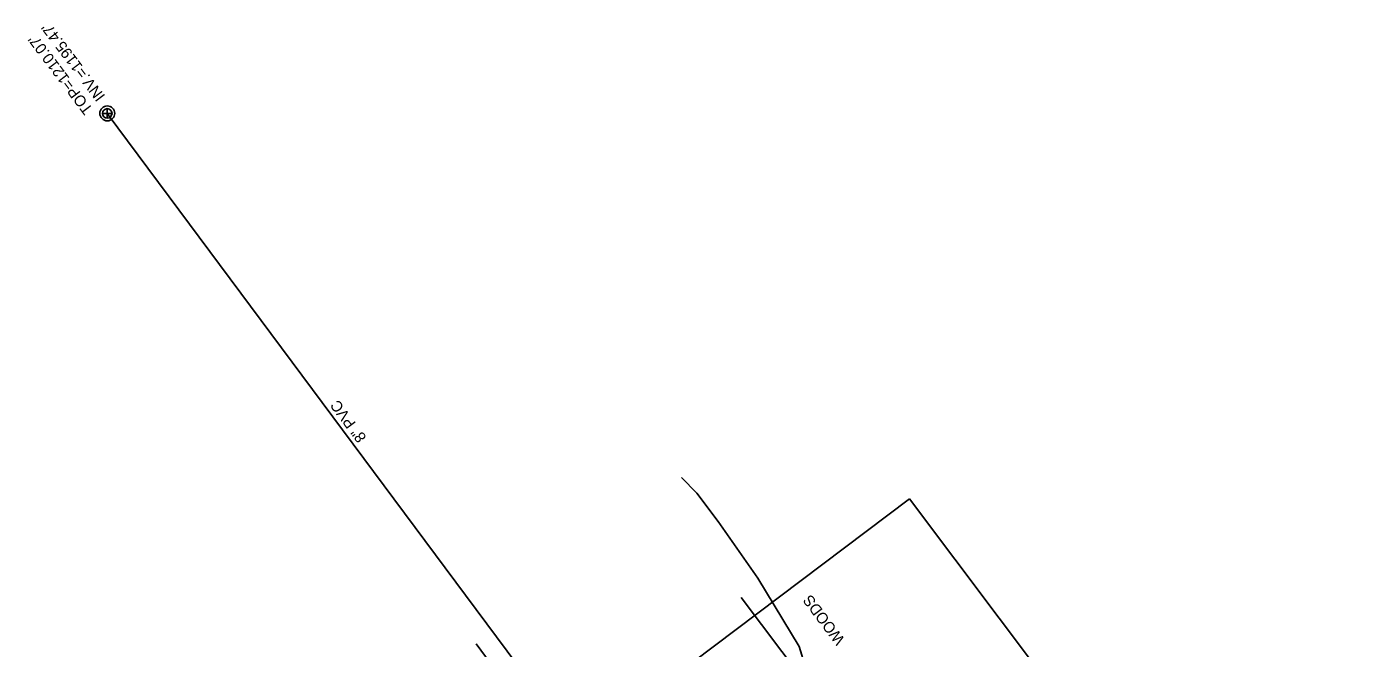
# Model space of a CAD drawing. Extents: x 1262092 to 1264624, y 774970 to 778314.
# Drawn here: x 1262121.8 to 1262603.1, y 778088.7 to 778313.7 of the extents above; entities that cross this region are included whole.
import ezdxf

# ---------------------------------------------------------------- set-up
doc = ezdxf.new("R2010")
doc.units = 0
for name, color, linetype in [('COGO Default Parcel', 7, 'Continuous'), ('Exist Right of Way Line', 7, 'Continuous'), ('Exist Roads EOP', 7, 'Continuous'), ('Exist Utilities Sanitary Sewer Manhole CELL', 7, 'Continuous'), ('Exist Utilities Sanitary Sewer Manhole Text', 7, 'Continuous'), ('Exist Utilities Sanitary Sewer UG Line', 7, 'Continuous'), ('Exist Utilities Sanitary Sewer UG Line Text', 7, 'Continuous'), ('Exist Vegetation Woods Line Text', 7, 'Continuous'), ('Prop Conc 5in Monolithic Keyed In Island', 7, 'Continuous')]:
    doc.layers.add(name, color=color, linetype=linetype)

# ---------------------------------------------------------------- blocks, each defined once
blk = doc.blocks.new('EXIST UTILITIES SANITARY SEWER MANHOLE')
at = {"layer": 'Exist Utilities Sanitary Sewer Manhole CELL'}
blk.add_lwpolyline([(0, 0.03425), (0, -0.03425), (0, 0), (0.03425, 0), (-0.03425, 0)], dxfattribs=at)
for radius in [0.05389, 0.03425]:
    blk.add_circle((0, 0), radius, dxfattribs=at)

msp = doc.modelspace()

# ---------------------------------------------------------------- linework, layer by layer
at = {"layer": 'COGO Default Parcel'}
for p, q in [((1262121.77, 777902.18), (1262441.33, 778142.77)), ((1262441.33, 778142.77), (1263481.78, 776760.76))]:
    msp.add_line(p, q, dxfattribs=at)
at = {"layer": 'Exist Right of Way Line'}
msp.add_line((1262380.46, 778107.12), (1263428.45, 776715.75), dxfattribs=at)
at = {"layer": 'Exist Roads EOP'}
msp.add_lwpolyline([(1262311.57, 778054.09), (1262307.15, 778059.68), (1262299.95, 778069.33), (1262289.62, 778083.4), (1262284.54, 778090.33)], dxfattribs=at)
at = {"layer": 'Exist Utilities Sanitary Sewer UG Line'}
msp.add_line((1262150.97, 778282.31), (1262537.27, 777762.91), dxfattribs=at)
at = {"layer": 'Prop Conc 5in Monolithic Keyed In Island'}
msp.add_lwpolyline([(1262475.13, 777991.95), (1262464.24, 778000.39), (1262444.63, 777997.8), (1262431.66, 777989.6), (1262421.56, 777990.43), (1262416.99, 778002.81), (1262411.38, 778012.03), (1262409.07, 778025.29), (1262413.02, 778032.03), (1262412.69, 778044.19), (1262408.56, 778052.02), (1262407.75, 778068.52), (1262401.46, 778089.29), (1262386.46, 778114.05), (1262372.11, 778134.59), (1262364.32, 778144.85), (1262358.8, 778150.49)], dxfattribs=at)

# ---------------------------------------------------------------- block references
at = {"layer": 'Exist Utilities Sanitary Sewer Manhole CELL', "xscale": 50, "yscale": 50}
msp.add_blockref('EXIST UTILITIES SANITARY SEWER MANHOLE', (1262150.97, 778282.31), dxfattribs=at)
msp.add_blockref('EXIST UTILITIES SANITARY SEWER MANHOLE', (1262150.97, 778282.31), dxfattribs=at)

# ---------------------------------------------------------------- texts
at = {"layer": 'Exist Utilities Sanitary Sewer Manhole Text'}
for s, rotation, p in [("INV.=1195.47'", 126.9874, (1262150.4, 778288.57)), ("TOP=1210.07'", 126.9746, (1262145.97, 778283.79))]:
    msp.add_text(s, height=4, rotation=rotation, dxfattribs=at).set_placement(p)
at = {"layer": 'Exist Utilities Sanitary Sewer UG Line Text'}
msp.add_text('8" PVC', height=4, rotation=126.6401, dxfattribs=at).set_placement((1262244.95, 778165.04))
at = {"layer": 'Exist Vegetation Woods Line Text'}
msp.add_text('WOODS', height=4, rotation=126.9874, dxfattribs=at).set_placement((1262418.17, 778091.82))

doc.saveas('drawing.dxf')
